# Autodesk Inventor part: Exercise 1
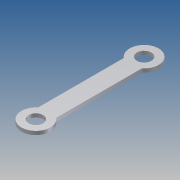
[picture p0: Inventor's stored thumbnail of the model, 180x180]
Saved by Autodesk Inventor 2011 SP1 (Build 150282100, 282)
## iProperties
Created: 2010-11
Part Number: Exercise 1
Document SubType Name: Modeling
Designer: SERGIO
Density: 1 g/cm^3
Author: SERGIO
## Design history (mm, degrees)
sketch "Sketch1"
  geometry: L1 (170.162, 234.352)-(170.162, -3.198); L2 (120.162, -3.198)-(120.162, 234.352); L3 (145.162, 265.577)-(145.162, -34.423); C1 r 20 at (145.162, 265.577); C2 r 20 at (145.162, -34.423); A1 r 40 centre (145.162, 265.577) between (170.162, 234.352) and (120.162, 234.352); A2 r 40 centre (145.162, -34.423) between (120.162, -3.198) and (170.162, -3.198); 1 further point
  constraints: 6 end point, 4 centre point, 4 point on circle, 2 coincident, 2 equal radius, 2 parallel, 1 vertical, 1 vertical alignment, 1 other
  dimensions: "d0" = 300 distance of A2.centre A1.centre; "d1" = 40 radius of A1; "d2" = 40 diameter of C1; "d3" = 50 distance between parallel lines of L1 L2
extrude "Extrusion1" new body sketch "Sketch1" distance "d5" = 10; taper "d6" = 0 deg
body "Solid1"
